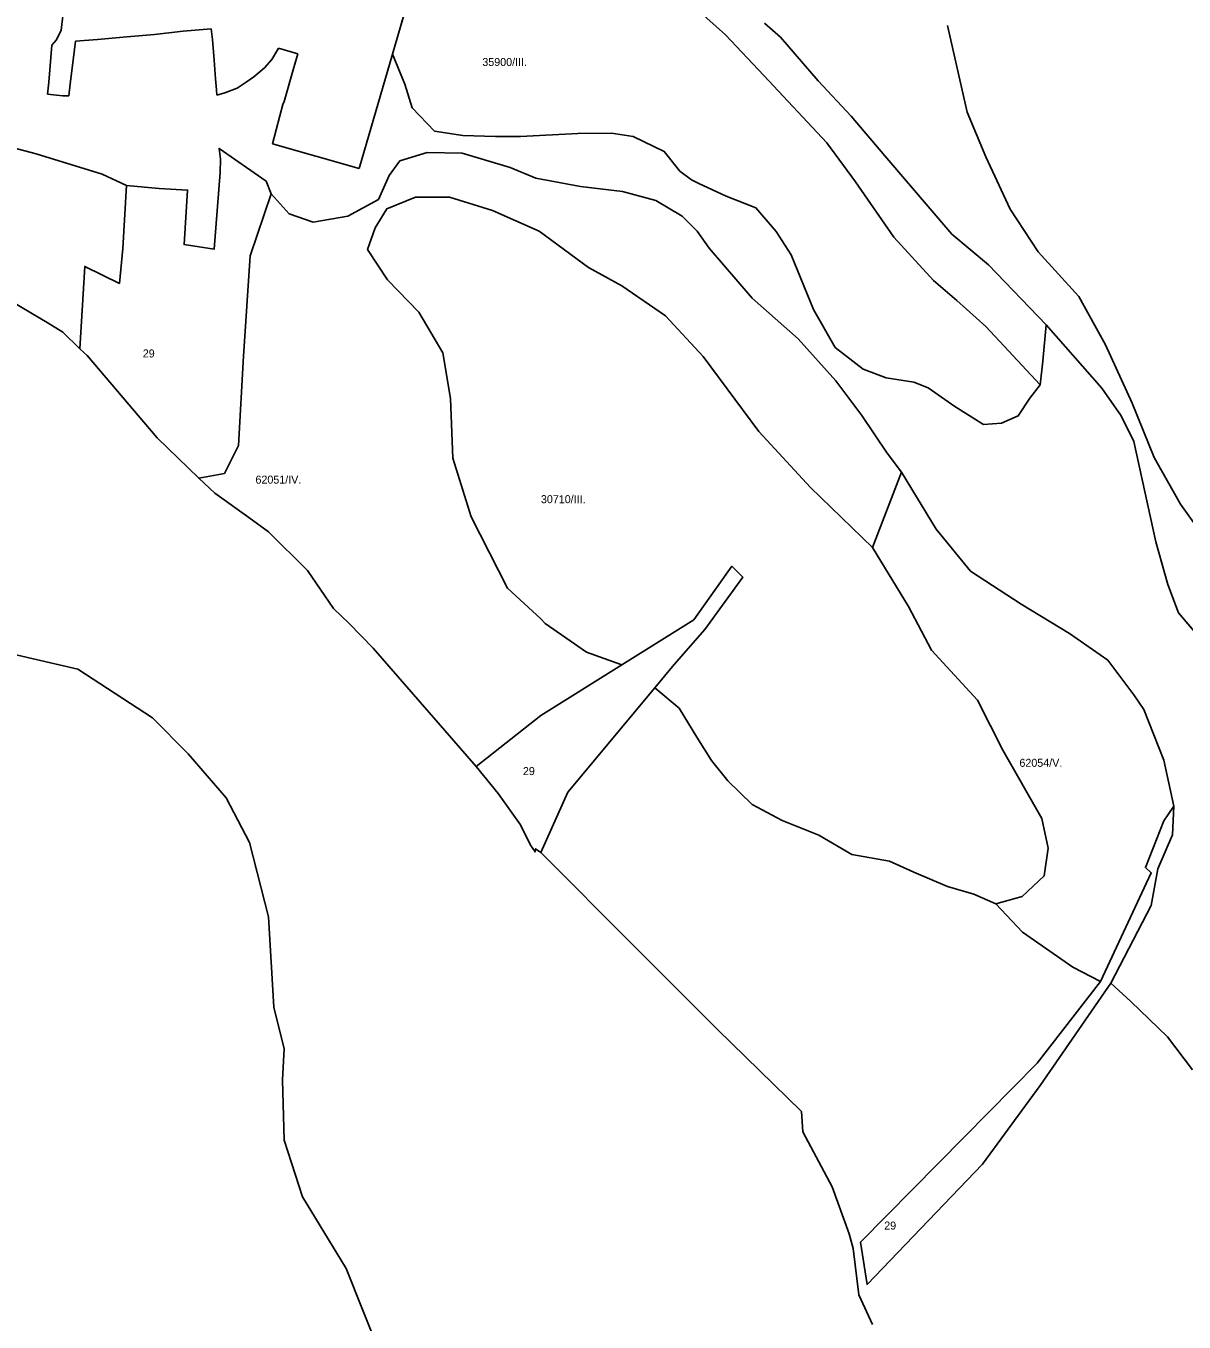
# Model space of a CAD drawing. Extents: x -521621 to -516761, y -1190184 to -1184927.
# Drawn here: x -518790 to -518211, y -1188092 to -1187445 of the extents above; entities that cross this region are included whole.
import ezdxf

# ---------------------------------------------------------------- set-up
doc = ezdxf.new("R2010")
doc.units = 0
doc.layers.add('BPEJ_s', color=7, linetype='Continuous')

msp = doc.modelspace()

# ---------------------------------------------------------------- linework, layer by layer
at = {"layer": 'BPEJ_s'}
for p, q in [((-518593.3, -1187413.32), (-518606.43, -1187458.65)), ((-518440.06, -1187448.96), (-518460.08, -1187430.81)), ((-518770.52, -1187434), (-518771.89, -1187446.71)), ((-518771.89, -1187446.71), (-518770.52, -1187434)), ((-518420.46, -1187443.14), (-518412.59, -1187450.15)), ((-518771.89, -1187446.71), (-518774.35, -1187451.49)), ((-518774.35, -1187451.49), (-518771.89, -1187446.71)), ((-518753.76, -1187451.33), (-518739.1, -1187450.04)), ((-518739.1, -1187450.04), (-518753.76, -1187451.33)), ((-518739.1, -1187450.04), (-518725.3, -1187448.74)), ((-518725.3, -1187448.74), (-518739.1, -1187450.04)), ((-518725.3, -1187448.74), (-518711.06, -1187447.23)), ((-518711.06, -1187447.23), (-518725.3, -1187448.74)), ((-518711.06, -1187447.23), (-518697.05, -1187445.94)), ((-518697.05, -1187445.94), (-518711.06, -1187447.23)), ((-518697.05, -1187445.94), (-518696.4, -1187451.33)), ((-518696.4, -1187451.33), (-518697.05, -1187445.94)), ((-518420.79, -1187469.37), (-518440.06, -1187448.96)), ((-518412.59, -1187450.15), (-518393.77, -1187472.04)), ((-518776.53, -1187454.09), (-518778.1, -1187472.56)), ((-518778.1, -1187472.56), (-518776.53, -1187454.09)), ((-518774.35, -1187451.49), (-518776.53, -1187454.09)), ((-518776.53, -1187454.09), (-518774.35, -1187451.49)), ((-518767.37, -1187473.68), (-518764.76, -1187452.19)), ((-518764.76, -1187452.19), (-518767.37, -1187473.68)), ((-518764.76, -1187452.19), (-518753.76, -1187451.33)), ((-518753.76, -1187451.33), (-518764.76, -1187452.19)), ((-518696.4, -1187451.33), (-518695.54, -1187461.69)), ((-518695.54, -1187461.69), (-518696.4, -1187451.33)), ((-518666.67, -1187461.38), (-518663.99, -1187456.89)), ((-518663.99, -1187456.89), (-518666.67, -1187461.38)), ((-518663.99, -1187456.89), (-518663.36, -1187455.62)), ((-518663.36, -1187455.62), (-518663.99, -1187456.89)), ((-518663.36, -1187455.62), (-518653.71, -1187458.46)), ((-518653.71, -1187458.46), (-518663.36, -1187455.62)), ((-518695.54, -1187461.69), (-518694.83, -1187470.9)), ((-518694.83, -1187470.9), (-518695.54, -1187461.69)), ((-518670.34, -1187465.49), (-518666.67, -1187461.38)), ((-518666.67, -1187461.38), (-518670.34, -1187465.49)), ((-518653.71, -1187458.46), (-518655.94, -1187466.45)), ((-518655.94, -1187466.45), (-518653.71, -1187458.46)), ((-518623, -1187515.83), (-518606.43, -1187458.65)), ((-518606.43, -1187458.65), (-518623, -1187515.83)), ((-518606.43, -1187458.65), (-518600.28, -1187473.59)), ((-518679.45, -1187472.72), (-518675.67, -1187469.94)), ((-518675.67, -1187469.94), (-518679.45, -1187472.72)), ((-518675.67, -1187469.94), (-518670.34, -1187465.49)), ((-518670.34, -1187465.49), (-518675.67, -1187469.94)), ((-518655.94, -1187466.45), (-518660.5, -1187482.32)), ((-518660.5, -1187482.32), (-518655.94, -1187466.45)), ((-518389.44, -1187503.02), (-518420.79, -1187469.37)), ((-518778.1, -1187472.56), (-518778.69, -1187478.57)), ((-518778.69, -1187478.57), (-518778.1, -1187472.56)), ((-518768.18, -1187479.55), (-518767.37, -1187473.68)), ((-518767.37, -1187473.68), (-518768.18, -1187479.55)), ((-518694.83, -1187470.9), (-518694.27, -1187476.5)), ((-518694.27, -1187476.5), (-518694.83, -1187470.9)), ((-518694.27, -1187476.5), (-518694.11, -1187479.1)), ((-518694.11, -1187479.1), (-518694.27, -1187476.5)), ((-518690.22, -1187478.05), (-518683.92, -1187475.56)), ((-518683.92, -1187475.56), (-518690.22, -1187478.05)), ((-518683.92, -1187475.56), (-518679.45, -1187472.72)), ((-518679.45, -1187472.72), (-518683.92, -1187475.56)), ((-518600.28, -1187473.59), (-518596.54, -1187485.39)), ((-518393.77, -1187472.04), (-518377.14, -1187489.56)), ((-518778.69, -1187478.57), (-518775.77, -1187478.95)), ((-518775.77, -1187478.95), (-518778.69, -1187478.57)), ((-518775.77, -1187478.95), (-518771.14, -1187479.48)), ((-518771.14, -1187479.48), (-518775.77, -1187478.95)), ((-518771.14, -1187479.48), (-518768.18, -1187479.55)), ((-518768.18, -1187479.55), (-518771.14, -1187479.48)), ((-518694.11, -1187479.1), (-518690.22, -1187478.05)), ((-518690.22, -1187478.05), (-518694.11, -1187479.1)), ((-518660.5, -1187482.32), (-518661.25, -1187483.84)), ((-518661.25, -1187483.84), (-518660.5, -1187482.32)), ((-518662.71, -1187489.43), (-518666.3, -1187503.51)), ((-518666.3, -1187503.51), (-518662.71, -1187489.43)), ((-518661.25, -1187483.84), (-518662.71, -1187489.43)), ((-518662.71, -1187489.43), (-518661.25, -1187483.84)), ((-518596.54, -1187485.39), (-518585.33, -1187497.19)), ((-518377.14, -1187489.56), (-518360.31, -1187509.5)), ((-518784.42, -1187508.4), (-518813.51, -1187500.79)), ((-518585.33, -1187497.19), (-518571.24, -1187499.21)), ((-518571.24, -1187499.21), (-518554.84, -1187499.78)), ((-518554.84, -1187499.78), (-518542.48, -1187499.78)), ((-518542.48, -1187499.78), (-518513.72, -1187498.34)), ((-518513.72, -1187498.34), (-518497.04, -1187498.05)), ((-518497.04, -1187498.05), (-518486.11, -1187499.78)), ((-518486.11, -1187499.78), (-518470.58, -1187507.26)), ((-518375.08, -1187522.38), (-518389.44, -1187503.02)), ((-518751.43, -1187518.6), (-518784.42, -1187508.4)), ((-518669.51, -1187522.14), (-518693.02, -1187505.72)), ((-518693.02, -1187505.72), (-518692.26, -1187511.17)), ((-518666.3, -1187503.51), (-518623, -1187515.83)), ((-518623, -1187515.83), (-518666.3, -1187503.51)), ((-518589.02, -1187507.76), (-518602.67, -1187511.89)), ((-518571.65, -1187508.17), (-518589.02, -1187507.76)), ((-518547.66, -1187515.21), (-518571.65, -1187508.17)), ((-518470.58, -1187507.26), (-518462.82, -1187517.05)), ((-518360.31, -1187509.5), (-518326.98, -1187548.56)), ((-518692.26, -1187511.17), (-518692.55, -1187517.7)), ((-518602.67, -1187511.89), (-518608.05, -1187519.34)), ((-518534.84, -1187520.58), (-518547.66, -1187515.21)), ((-518739.36, -1187524.31), (-518751.43, -1187518.6)), ((-518692.55, -1187517.7), (-518695.48, -1187556.05)), ((-518667.05, -1187528.51), (-518669.51, -1187522.14)), ((-518608.05, -1187519.34), (-518613.42, -1187531.34)), ((-518512.5, -1187524.72), (-518534.84, -1187520.58)), ((-518462.82, -1187517.05), (-518457.06, -1187521.36)), ((-518457.06, -1187521.36), (-518453.33, -1187523.33)), ((-518355.88, -1187550.04), (-518375.08, -1187522.38)), ((-518722.93, -1187525.73), (-518739.36, -1187524.31)), ((-518708.77, -1187526.58), (-518722.93, -1187525.73)), ((-518710.52, -1187553.79), (-518708.77, -1187526.58)), ((-518658.09, -1187538.38), (-518667.05, -1187528.51)), ((-518491.41, -1187527.21), (-518512.5, -1187524.72)), ((-518474.87, -1187531.76), (-518491.41, -1187527.21)), ((-518453.33, -1187523.33), (-518439.7, -1187529.54)), ((-518613.42, -1187531.34), (-518628.73, -1187539.62)), ((-518461.63, -1187539.62), (-518474.87, -1187531.76)), ((-518439.7, -1187529.54), (-518424.82, -1187535.43)), ((-518424.82, -1187535.43), (-518414.6, -1187547.21)), ((-518646.1, -1187542.52), (-518658.09, -1187538.38)), ((-518628.73, -1187539.62), (-518646.1, -1187542.52)), ((-518454.19, -1187547.07), (-518461.63, -1187539.62)), ((-518448.16, -1187555.63), (-518454.19, -1187547.07)), ((-518414.6, -1187547.21), (-518407.16, -1187558.99)), ((-518695.48, -1187556.05), (-518710.52, -1187553.79)), ((-518336.09, -1187571.71), (-518355.88, -1187550.04)), ((-518326.98, -1187548.56), (-518308.67, -1187563.99)), ((-518426.7, -1187580.55), (-518448.16, -1187555.63)), ((-518407.16, -1187558.99), (-518396.01, -1187586.27)), ((-518308.67, -1187563.99), (-518279.79, -1187593.89)), ((-518324.43, -1187581.73), (-518336.09, -1187571.71)), ((-518403.71, -1187600.87), (-518426.7, -1187580.55)), ((-518396.01, -1187586.27), (-518385.17, -1187605.18)), ((-518309.99, -1187594.71), (-518324.43, -1187581.73)), ((-518282.77, -1187623.84), (-518309.99, -1187594.71)), ((-518281.37, -1187612), (-518279.79, -1187593.89)), ((-518279.79, -1187593.89), (-518281.37, -1187612)), ((-518279.79, -1187593.89), (-518251.95, -1187625.46)), ((-518384.94, -1187621.96), (-518403.71, -1187600.87)), ((-518385.17, -1187605.18), (-518371.22, -1187616.03)), ((-518282.77, -1187623.84), (-518281.37, -1187612)), ((-518281.37, -1187612), (-518282.77, -1187623.84)), ((-518371.22, -1187616.03), (-518359.76, -1187620.37)), ((-518371.91, -1187639.21), (-518384.94, -1187621.96)), ((-518359.76, -1187620.37), (-518345.82, -1187622.54)), ((-518345.82, -1187622.54), (-518338.69, -1187625.33)), ((-518338.69, -1187625.33), (-518325.37, -1187634.64)), ((-518287.88, -1187630.6), (-518282.77, -1187623.84)), ((-518251.95, -1187625.46), (-518242.28, -1187639.37)), ((-518293.76, -1187639.29), (-518287.88, -1187630.6)), ((-518325.37, -1187634.64), (-518311.11, -1187643.63)), ((-518359.27, -1187658), (-518371.91, -1187639.21)), ((-518311.11, -1187643.63), (-518302.13, -1187643.01)), ((-518302.13, -1187643.01), (-518293.76, -1187639.29)), ((-518242.28, -1187639.37), (-518236.03, -1187652.27)), ((-518351.99, -1187667.58), (-518359.27, -1187658)), ((-518236.03, -1187652.27), (-518224.99, -1187702.39)), ((-518334.75, -1187695.96), (-518351.99, -1187667.58)), ((-518317.5, -1187717.04), (-518334.75, -1187695.96)), ((-518224.99, -1187702.39), (-518218.97, -1187723.71)), ((-518292.21, -1187733.53), (-518317.5, -1187717.04)), ((-518218.97, -1187723.71), (-518213.64, -1187737.85)), ((-518268.08, -1187748.1), (-518292.21, -1187733.53)), ((-518213.64, -1187737.85), (-518179.13, -1187778.41)), ((-518248.92, -1187761.52), (-518268.08, -1187748.1)), ((-518235.89, -1187778.77), (-518248.92, -1187761.52)), ((-518230.91, -1187786.05), (-518235.89, -1187778.77)), ((-518220.95, -1187811.36), (-518230.91, -1187786.05)), ((-518216.02, -1187834.34), (-518220.95, -1187811.36)), ((-518216.73, -1187848.74), (-518216.02, -1187834.34)), ((-518223.93, -1187865.78), (-518216.73, -1187848.74)), ((-518227.29, -1187884.03), (-518223.93, -1187865.78)), ((-518247.52, -1187922.9), (-518227.29, -1187884.03)), ((-518237.5, -1187932.03), (-518247.52, -1187922.9)), ((-518219.21, -1187949.69), (-518237.5, -1187932.03)), ((-518206.66, -1187966.08), (-518219.21, -1187949.69))]:
    msp.add_line(p, q, dxfattribs=at)
for points in [[(-518460.08, -1187430.81), (-518440.06, -1187448.96), (-518420.79, -1187469.37), (-518389.44, -1187503.02), (-518375.08, -1187522.38), (-518355.88, -1187550.04), (-518336.09, -1187571.71), (-518324.43, -1187581.73), (-518309.99, -1187594.71), (-518282.77, -1187623.84), (-518287.88, -1187630.6), (-518293.76, -1187639.29), (-518302.13, -1187643.01), (-518311.11, -1187643.63), (-518325.37, -1187634.64), (-518338.69, -1187625.33), (-518345.82, -1187622.54), (-518359.76, -1187620.37), (-518371.22, -1187616.03), (-518385.17, -1187605.18), (-518396.01, -1187586.27), (-518407.16, -1187558.99), (-518414.6, -1187547.21), (-518424.82, -1187535.43), (-518439.7, -1187529.54), (-518453.33, -1187523.33), (-518457.06, -1187521.36), (-518462.82, -1187517.05), (-518470.58, -1187507.26), (-518486.11, -1187499.78), (-518497.04, -1187498.05), (-518513.72, -1187498.34), (-518542.48, -1187499.78), (-518554.84, -1187499.78), (-518571.24, -1187499.21), (-518585.33, -1187497.19), (-518596.54, -1187485.39), (-518600.28, -1187473.59), (-518606.43, -1187458.65), (-518593.3, -1187413.32)], [(-518179.13, -1187778.41), (-518213.64, -1187737.85), (-518218.97, -1187723.71), (-518224.99, -1187702.39), (-518236.03, -1187652.27), (-518242.28, -1187639.37), (-518251.95, -1187625.46), (-518279.79, -1187593.89), (-518308.67, -1187563.99), (-518326.98, -1187548.56), (-518360.31, -1187509.5), (-518377.14, -1187489.56), (-518393.77, -1187472.04), (-518412.59, -1187450.15), (-518420.46, -1187443.14)], [(-518182.04, -1187726.48), (-518212.64, -1187683.44), (-518225.88, -1187660.26), (-518236.75, -1187633.08), (-518250.08, -1187603.94), (-518263.4, -1187579.76), (-518283.85, -1187557.44), (-518297.79, -1187536.05), (-518309.87, -1187510), (-518319.17, -1187487.68), (-518329.08, -1187444.28)], [(-518329.08, -1187444.28), (-518319.17, -1187487.68), (-518309.87, -1187510), (-518297.79, -1187536.05), (-518283.85, -1187557.44), (-518263.4, -1187579.76), (-518250.08, -1187603.94), (-518236.75, -1187633.08), (-518225.88, -1187660.26), (-518212.64, -1187683.44), (-518182.04, -1187726.48)], [(-518813.51, -1187500.79), (-518784.42, -1187508.4), (-518751.43, -1187518.6), (-518739.36, -1187524.31), (-518741.11, -1187555.8), (-518742.87, -1187573.2), (-518760.17, -1187564.67), (-518762.67, -1187605.82), (-518771.03, -1187597.6), (-518778.94, -1187592.67), (-518796.09, -1187582.5)], [(-518796.09, -1187582.5), (-518778.94, -1187592.67), (-518771.03, -1187597.6), (-518762.67, -1187605.82), (-518759, -1187609.21), (-518723.89, -1187650.3), (-518703.18, -1187670.52), (-518695.13, -1187677.93), (-518678.21, -1187690.17), (-518668.36, -1187697.39), (-518648.89, -1187716.63), (-518635.92, -1187735.63), (-518627.98, -1187743.09), (-518616, -1187755.54), (-518564.51, -1187814.54), (-518553.67, -1187828.1), (-518542.49, -1187843.69), (-518537.41, -1187853.86), (-518535.18, -1187857.25), (-518534.87, -1187855.67), (-518532.35, -1187857.56), (-518486.1, -1187903.85), (-518443.93, -1187946.05), (-518402.09, -1187986.99), (-518401.33, -1187997.12), (-518386.62, -1188024.55), (-518378.15, -1188048.15), (-518376.14, -1188055.41), (-518373.32, -1188078.61), (-518366.54, -1188093.37)], [(-518612.92, -1188107.21), (-518629.6, -1188065.48), (-518651.29, -1188029.6), (-518660.46, -1188001.22), (-518661.29, -1187971.18), (-518660.49, -1187955.69), (-518665.7, -1187934.84), (-518668.3, -1187889.66), (-518677.89, -1187852.5), (-518689.45, -1187830.25), (-518708.43, -1187808.3), (-518726.22, -1187790.2), (-518763.58, -1187765.87), (-518805.39, -1187756.37)], [(-518805.39, -1187756.37), (-518763.58, -1187765.87), (-518726.22, -1187790.2), (-518708.43, -1187808.3), (-518689.45, -1187830.25), (-518677.89, -1187852.5), (-518668.3, -1187889.66), (-518665.7, -1187934.84), (-518660.49, -1187955.69), (-518661.29, -1187971.18), (-518660.46, -1188001.22), (-518651.29, -1188029.6), (-518629.6, -1188065.48), (-518612.92, -1188107.21)], [(-518366.54, -1188093.37), (-518373.32, -1188078.61), (-518376.14, -1188055.41), (-518378.15, -1188048.15), (-518386.62, -1188024.55), (-518401.33, -1187997.12), (-518402.09, -1187986.99), (-518443.93, -1187946.05), (-518486.1, -1187903.85), (-518532.35, -1187857.56), (-518518.77, -1187827.42), (-518475.28, -1187775.29), (-518463.15, -1187785.5), (-518454.36, -1187799.99), (-518447.03, -1187811.54), (-518438.78, -1187821.81), (-518426.7, -1187833.59), (-518411.76, -1187841.65), (-518393.37, -1187848.93), (-518376.89, -1187858.52), (-518358.12, -1187861.97), (-518345.86, -1187867.33), (-518329, -1187874.62), (-518315.97, -1187878.45), (-518304.93, -1187883.29), (-518291.53, -1187897.33), (-518266.43, -1187914.79), (-518252.55, -1187922.03), (-518284.22, -1187962.9), (-518320.72, -1187999.74), (-518372.51, -1188052.19), (-518369.28, -1188073.36), (-518311.65, -1188013.26), (-518282.69, -1187974.05), (-518247.52, -1187922.9), (-518237.5, -1187932.03), (-518219.21, -1187949.69), (-518206.66, -1187966.08)]]:
    msp.add_lwpolyline(points, dxfattribs=at)
for points in [[(-518762.67, -1187605.82), (-518760.17, -1187564.67), (-518742.87, -1187573.2), (-518741.11, -1187555.8), (-518739.36, -1187524.31), (-518722.93, -1187525.73), (-518708.77, -1187526.58), (-518710.52, -1187553.79), (-518695.48, -1187556.05), (-518692.55, -1187517.7), (-518692.26, -1187511.17), (-518693.02, -1187505.72), (-518669.51, -1187522.14), (-518667.05, -1187528.51), (-518677.5, -1187559.44), (-518680.76, -1187609.53), (-518683.38, -1187654.19), (-518690.34, -1187668.12), (-518703.18, -1187670.52), (-518723.89, -1187650.3), (-518759, -1187609.21)], [(-518703.18, -1187670.52), (-518690.34, -1187668.12), (-518683.38, -1187654.19), (-518680.76, -1187609.53), (-518677.5, -1187559.44), (-518667.05, -1187528.51), (-518658.09, -1187538.38), (-518646.1, -1187542.52), (-518628.73, -1187539.62), (-518613.42, -1187531.34), (-518608.05, -1187519.34), (-518602.67, -1187511.89), (-518589.02, -1187507.76), (-518571.65, -1187508.17), (-518547.66, -1187515.21), (-518534.84, -1187520.58), (-518512.5, -1187524.72), (-518491.41, -1187527.21), (-518474.87, -1187531.76), (-518461.63, -1187539.62), (-518454.19, -1187547.07), (-518448.16, -1187555.63), (-518426.7, -1187580.55), (-518403.71, -1187600.87), (-518384.94, -1187621.96), (-518371.91, -1187639.21), (-518359.27, -1187658), (-518351.99, -1187667.58), (-518366.55, -1187705.16), (-518397.58, -1187675.25), (-518423.26, -1187647.26), (-518451.23, -1187609.69), (-518470, -1187589.37), (-518491.84, -1187574.42), (-518508.37, -1187565.28), (-518533.18, -1187547.07), (-518556.35, -1187536.73), (-518577.85, -1187530.1), (-518594.81, -1187530.1), (-518609.29, -1187535.9), (-518615.08, -1187545.42), (-518618.8, -1187556.18), (-518608.87, -1187571.49), (-518593.16, -1187587.63), (-518581.16, -1187607.91), (-518577.44, -1187630.67), (-518576.2, -1187660.47), (-518567.1, -1187689.85), (-518548.9, -1187725.44), (-518532.24, -1187740.76), (-518530.04, -1187743.14), (-518509.52, -1187757.45), (-518491.77, -1187763.79), (-518532.32, -1187789.11), (-518564.51, -1187814.54), (-518616, -1187755.54), (-518627.98, -1187743.09), (-518635.92, -1187735.63), (-518648.89, -1187716.63), (-518668.36, -1187697.39), (-518678.21, -1187690.17), (-518695.13, -1187677.93)], [(-518491.77, -1187763.79), (-518509.52, -1187757.45), (-518530.04, -1187743.14), (-518532.24, -1187740.76), (-518548.9, -1187725.44), (-518567.1, -1187689.85), (-518576.2, -1187660.47), (-518577.44, -1187630.67), (-518581.16, -1187607.91), (-518593.16, -1187587.63), (-518608.87, -1187571.49), (-518618.8, -1187556.18), (-518615.08, -1187545.42), (-518609.29, -1187535.9), (-518594.81, -1187530.1), (-518577.85, -1187530.1), (-518556.35, -1187536.73), (-518533.18, -1187547.07), (-518508.37, -1187565.28), (-518491.84, -1187574.42), (-518470, -1187589.37), (-518451.23, -1187609.69), (-518423.26, -1187647.26), (-518397.58, -1187675.25), (-518366.55, -1187705.16), (-518348.54, -1187734.68), (-518342.03, -1187746.95), (-518337.04, -1187756.53), (-518314.06, -1187781.45), (-518301.41, -1187806.37), (-518281.87, -1187840.5), (-518278.8, -1187855.45), (-518280.72, -1187869.25), (-518291.83, -1187879.6), (-518304.93, -1187883.29), (-518315.97, -1187878.45), (-518329, -1187874.62), (-518345.86, -1187867.33), (-518358.12, -1187861.97), (-518376.89, -1187858.52), (-518393.37, -1187848.93), (-518411.76, -1187841.65), (-518426.7, -1187833.59), (-518438.78, -1187821.81), (-518447.03, -1187811.54), (-518454.36, -1187799.99), (-518463.15, -1187785.5), (-518475.28, -1187775.29), (-518465.59, -1187763.68), (-518450.34, -1187746.05), (-518431.37, -1187719.94), (-518436.79, -1187714.52), (-518455.76, -1187741.3)], [(-518366.55, -1187705.16), (-518351.99, -1187667.58), (-518334.75, -1187695.96), (-518317.5, -1187717.04), (-518292.21, -1187733.53), (-518268.08, -1187748.1), (-518248.92, -1187761.52), (-518235.89, -1187778.77), (-518230.91, -1187786.05), (-518220.95, -1187811.36), (-518216.02, -1187834.34), (-518221.05, -1187841.78), (-518230.17, -1187865.06), (-518227.29, -1187867.7), (-518252.55, -1187922.03), (-518266.43, -1187914.79), (-518291.53, -1187897.33), (-518304.93, -1187883.29), (-518291.83, -1187879.6), (-518280.72, -1187869.25), (-518278.8, -1187855.45), (-518281.87, -1187840.5), (-518301.41, -1187806.37), (-518314.06, -1187781.45), (-518337.04, -1187756.53), (-518342.03, -1187746.95), (-518348.54, -1187734.68)], [(-518564.51, -1187814.54), (-518532.32, -1187789.11), (-518491.77, -1187763.79), (-518455.76, -1187741.3), (-518436.79, -1187714.52), (-518431.37, -1187719.94), (-518450.34, -1187746.05), (-518465.59, -1187763.68), (-518475.28, -1187775.29), (-518518.77, -1187827.42), (-518532.35, -1187857.56), (-518534.87, -1187855.67), (-518535.18, -1187857.25), (-518537.41, -1187853.86), (-518542.49, -1187843.69), (-518553.67, -1187828.1)], [(-518252.55, -1187922.03), (-518227.29, -1187867.7), (-518230.17, -1187865.06), (-518221.05, -1187841.78), (-518216.02, -1187834.34), (-518216.73, -1187848.74), (-518223.93, -1187865.78), (-518227.29, -1187884.03), (-518247.52, -1187922.9), (-518282.69, -1187974.05), (-518311.65, -1188013.26), (-518369.28, -1188073.36), (-518372.51, -1188052.19), (-518320.72, -1187999.74), (-518284.22, -1187962.9)]]:
    msp.add_lwpolyline(points, close=True, dxfattribs=at)

# ---------------------------------------------------------------- texts
for s, p in [('35900/III.', (-518561.5, -1187464.56)), ('29', (-518731.15, -1187610.19)), ('62051/IV.', (-518674.85, -1187673.25)), ('30710/III.', (-518532.22, -1187683.01)), ('62054/V.', (-518293.13, -1187814.75)), ('29', (-518541.23, -1187818.88)), ('29', (-518360.69, -1188045.97))]:
    msp.add_text(s, height=4, dxfattribs=at).set_placement(p)

doc.saveas('drawing.dxf')
